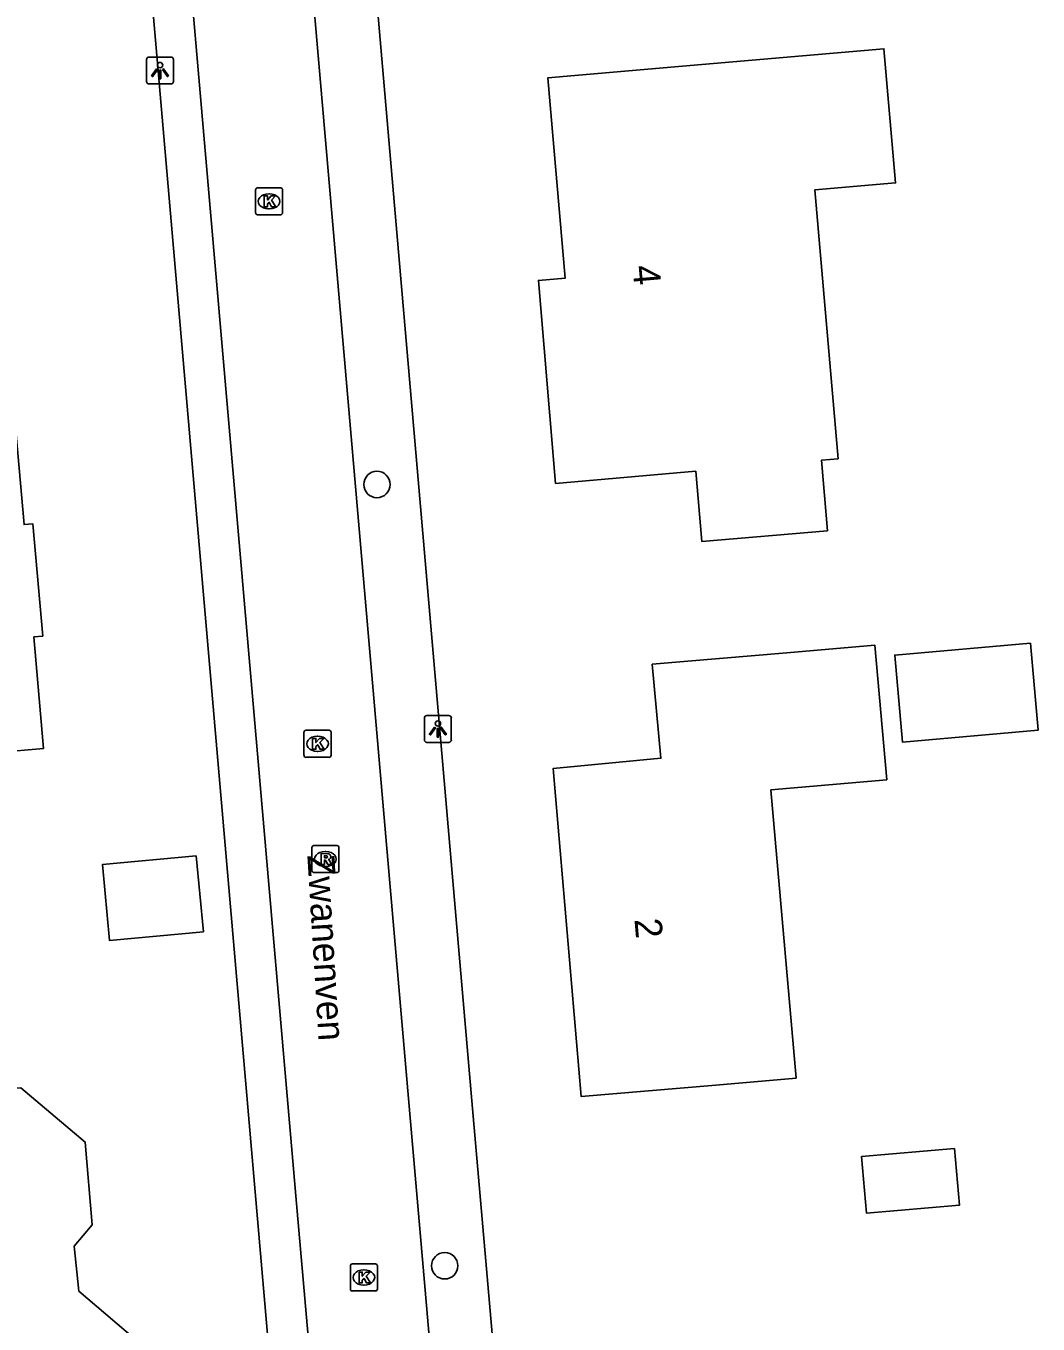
# Model space of a CAD drawing. Extents: x 163427 to 164190, y 380331 to 381641.
# Drawn here: x 164026.23 to 164063.7, y 381087.05 to 381135.13 of the extents above; entities that cross this region are included whole.
import ezdxf

# ---------------------------------------------------------------- set-up
doc = ezdxf.new("R2010")
doc.units = 0
for name, color, linetype in [('IMGEO_Boom', 7, 'Continuous'), ('IMGEO_Kolk', 7, 'Continuous'), ('IMGEO_Lichtpunt', 7, 'Continuous'), ('IMGEO_Openbare_ruimte_label', 7, 'Continuous'), ('IMGEO_Pand', 7, 'Continuous'), ('IMGEO_Pand_nummerreeks', 7, 'Continuous'), ('IMGEO_Rijbaan_lokaal_open', 7, 'Continuous'), ('IMGEO_Rioolput', 7, 'Continuous'), ('IMGEO_Voetpad_open', 7, 'Continuous')]:
    doc.layers.add(name, color=color, linetype=linetype)

msp = doc.modelspace()

# ---------------------------------------------------------------- linework, layer by layer
at = {"layer": 'IMGEO_Boom'}
for centre in [(164039.225, 381118.148), (164041.732, 381089.207)]:
    msp.add_circle(centre, 0.489, dxfattribs=at)
at = {"layer": 'IMGEO_Kolk'}
for p, q in [((164034.728, 381128.211), (164034.728, 381129.063)), ((164034.803, 381129.137), (164035.655, 381129.137)), ((164035.216, 381128.917), (164035.241, 381128.917)), ((164035.729, 381129.063), (164035.729, 381128.211)), ((164035.239, 381128.357), (164035.214, 381128.357)), ((164035.655, 381128.137), (164034.803, 381128.137)), ((164036.522, 381108.115), (164036.522, 381108.967)), ((164036.597, 381109.041), (164037.449, 381109.041)), ((164037.01, 381108.821), (164037.035, 381108.821)), ((164037.523, 381108.967), (164037.523, 381108.115)), ((164037.033, 381108.261), (164037.008, 381108.261)), ((164037.449, 381108.041), (164036.597, 381108.041)), ((164038.238, 381088.346), (164038.238, 381089.198)), ((164038.313, 381089.272), (164039.165, 381089.272)), ((164038.726, 381089.052), (164038.751, 381089.052)), ((164039.239, 381089.198), (164039.239, 381088.346)), ((164038.749, 381088.492), (164038.724, 381088.492)), ((164039.165, 381088.272), (164038.313, 381088.272))]:
    msp.add_line(p, q, dxfattribs=at)
for points in [[(164034.728, 381128.211), (164034.728, 381129.063)], [(164034.803, 381129.137), (164035.655, 381129.137)], [(164035.049, 381128.837), (164035.172, 381128.837), (164035.172, 381128.686), (164035.302, 381128.837), (164035.466, 381128.837), (164035.32, 381128.686), (164035.473, 381128.437), (164035.321, 381128.437), (164035.236, 381128.601), (164035.172, 381128.534), (164035.172, 381128.437), (164035.049, 381128.437), (164035.049, 381128.837)], [(164035.729, 381129.063), (164035.729, 381128.211)], [(164035.655, 381128.137), (164034.803, 381128.137)], [(164036.522, 381108.115), (164036.522, 381108.967)], [(164036.597, 381109.041), (164037.449, 381109.041)], [(164036.843, 381108.741), (164036.966, 381108.741), (164036.966, 381108.59), (164037.096, 381108.741), (164037.26, 381108.741), (164037.114, 381108.59), (164037.267, 381108.341), (164037.115, 381108.341), (164037.03, 381108.505), (164036.966, 381108.438), (164036.966, 381108.341), (164036.843, 381108.341), (164036.843, 381108.741)], [(164037.523, 381108.967), (164037.523, 381108.115)], [(164037.449, 381108.041), (164036.597, 381108.041)], [(164038.238, 381088.346), (164038.238, 381089.198)], [(164038.313, 381089.272), (164039.165, 381089.272)], [(164038.559, 381088.972), (164038.682, 381088.972), (164038.682, 381088.821), (164038.812, 381088.972), (164038.976, 381088.972), (164038.83, 381088.821), (164038.983, 381088.572), (164038.831, 381088.572), (164038.746, 381088.736), (164038.682, 381088.669), (164038.682, 381088.572), (164038.559, 381088.572), (164038.559, 381088.972)], [(164039.239, 381089.198), (164039.239, 381088.346)], [(164039.165, 381088.272), (164038.313, 381088.272)]]:
    msp.add_lwpolyline(points, dxfattribs=at)
for centre, start, end in [((164034.805, 381129.061), 91.552, 178.448), ((164034.805, 381129.061), 91.552, 178.448), ((164035.653, 381129.061), 1.552, 88.448), ((164035.653, 381129.061), 1.552, 88.448), ((164034.805, 381128.213), 181.552, 268.448), ((164034.805, 381128.213), 181.552, 268.448), ((164035.653, 381128.213), 271.552, 358.448), ((164035.653, 381128.213), 271.552, 358.448), ((164036.599, 381108.965), 91.552, 178.448), ((164036.599, 381108.965), 91.552, 178.448), ((164037.447, 381108.965), 1.552, 88.448), ((164037.447, 381108.965), 1.552, 88.448), ((164036.599, 381108.117), 181.552, 268.448), ((164036.599, 381108.117), 181.552, 268.448), ((164037.447, 381108.117), 271.552, 358.448), ((164037.447, 381108.117), 271.552, 358.448), ((164038.315, 381089.196), 91.552, 178.448), ((164038.315, 381089.196), 91.552, 178.448), ((164039.163, 381089.196), 1.552, 88.448), ((164039.163, 381089.196), 1.552, 88.448), ((164038.315, 381088.348), 181.552, 268.448), ((164038.315, 381088.348), 181.552, 268.448), ((164039.163, 381088.348), 271.552, 358.448), ((164039.163, 381088.348), 271.552, 358.448)]:
    msp.add_arc(centre, 0.0765, start, end, dxfattribs=at)
for centre, major_axis, ratio, start_param, end_param in [((164035.215, 381128.637), (-0.387, 0.002), 0.722429, 4.712389, 7.853982), ((164035.24, 381128.637), (-0.39, 0.002), 0.717154, 1.570796, 4.712389), ((164037.009, 381108.541), (-0.387, 0.002), 0.722429, 4.712389, 7.853982), ((164037.034, 381108.541), (-0.39, 0.002), 0.717154, 1.570796, 4.712389), ((164038.725, 381088.772), (-0.387, 0.002), 0.722429, 4.712389, 7.853982), ((164038.75, 381088.772), (-0.39, 0.002), 0.717154, 1.570796, 4.712389)]:
    msp.add_ellipse(centre, major_axis=major_axis, ratio=ratio, start_param=start_param, end_param=end_param, dxfattribs=at)
at = {"layer": 'IMGEO_Lichtpunt'}
for p, q in [((164030.692, 381133.885), (164030.692, 381133.078)), ((164030.692, 381133.885), (164030.692, 381133.078)), ((164031.594, 381133.98), (164030.786, 381133.98)), ((164031.594, 381133.98), (164030.786, 381133.98)), ((164031.688, 381133.078), (164031.688, 381133.885)), ((164031.688, 381133.078), (164031.688, 381133.885)), ((164030.786, 381132.984), (164031.594, 381132.984)), ((164030.786, 381132.984), (164031.594, 381132.984)), ((164041.884, 381109.591), (164041.076, 381109.591)), ((164041.884, 381109.591), (164041.076, 381109.591)), ((164040.982, 381109.496), (164040.982, 381108.689)), ((164040.982, 381109.496), (164040.982, 381108.689)), ((164041.978, 381108.689), (164041.978, 381109.496)), ((164041.978, 381108.689), (164041.978, 381109.496)), ((164041.076, 381108.595), (164041.884, 381108.595)), ((164041.076, 381108.595), (164041.884, 381108.595))]:
    msp.add_line(p, q, dxfattribs=at)
for points in [[(164031.066, 381133.549), (164031.105, 381133.521), (164030.917, 381133.259), (164030.879, 381133.286), (164031.066, 381133.549)], [(164031.168, 381133.501), (164031.215, 381133.501), (164031.215, 381133.179), (164031.168, 381133.179), (164031.168, 381133.501)], [(164031.278, 381133.521), (164031.316, 381133.548), (164031.503, 381133.286), (164031.464, 381133.258), (164031.278, 381133.521)], [(164041.356, 381109.16), (164041.395, 381109.132), (164041.207, 381108.87), (164041.169, 381108.897), (164041.356, 381109.16)], [(164041.458, 381109.112), (164041.505, 381109.112), (164041.505, 381108.79), (164041.458, 381108.79), (164041.458, 381109.112)], [(164041.568, 381109.132), (164041.606, 381109.159), (164041.793, 381108.897), (164041.754, 381108.869), (164041.568, 381109.132)]]:
    msp.add_lwpolyline(points, dxfattribs=at)
for centre in [(164031.191, 381133.683), (164041.481, 381109.294)]:
    msp.add_circle(centre, 0.0994, dxfattribs=at)
for centre, start, end in [((164030.786, 381133.885), 90, 180), ((164030.786, 381133.885), 90, 180), ((164031.594, 381133.885), 0, 90), ((164031.594, 381133.885), 0, 90), ((164030.786, 381133.078), 180, 270), ((164030.786, 381133.078), 180, 270), ((164031.594, 381133.078), 270, 0), ((164031.594, 381133.078), 270, 360), ((164041.076, 381109.496), 90, 180), ((164041.076, 381109.496), 90, 180), ((164041.884, 381109.496), 0, 90), ((164041.884, 381109.496), 0, 90), ((164041.076, 381108.689), 180, 270), ((164041.076, 381108.689), 180, 270), ((164041.884, 381108.689), 270, 0), ((164041.884, 381108.689), 270, 360)]:
    msp.add_arc(centre, 0.0946, start, end, dxfattribs=at)
at = {"layer": 'IMGEO_Pand'}
for points in [[(164056.308, 381119.097), (164055.68, 381119.043), (164055.907, 381116.435), (164051.259, 381116.03), (164051.032, 381118.639), (164045.837, 381118.186), (164045.204, 381125.706), (164046.197, 381125.792), (164045.553, 381133.214), (164050.535, 381133.644), (164057.995, 381134.288), (164058.427, 381129.321), (164055.441, 381129.061), (164056.308, 381119.097)], [(164022.897, 381123.306), (164023.13, 381120.616), (164025.79, 381120.844), (164026.154, 381116.66), (164026.483, 381116.689), (164026.847, 381112.53), (164026.52, 381112.502), (164026.87, 381108.365), (164023.483, 381108.073), (164023.561, 381107.178)], [(164054.748, 381096.152), (164051.772, 381095.898), (164046.79, 381095.474), (164045.751, 381107.631), (164049.742, 381108.005), (164049.416, 381111.488), (164054.398, 381111.914), (164057.666, 381112.193), (164058.103, 381107.211), (164053.81, 381106.834), (164054.748, 381096.152)], [(164063.704, 381109.045), (164058.68, 381108.607), (164058.399, 381111.831), (164063.423, 381112.269), (164063.704, 381109.045)], [(164032.534, 381104.395), (164029.056, 381104.07), (164029.319, 381101.257), (164032.797, 381101.582), (164032.534, 381104.395)], [(164026.032, 381095.799), (164028.413, 381093.79), (164028.676, 381090.719), (164028.013, 381089.931), (164028.186, 381088.27), (164030.609, 381086.198), (164030.975, 381081.841), (164028.167, 381078.484), (164023.8, 381078.126), (164019.504, 381081.734), (164019.312, 381084.422), (164021.285, 381086.767), (164022.893, 381088.678), (164021.235, 381090.089), (164020.964, 381093.173), (164022.955, 381095.537), (164026.032, 381095.799)], [(164060.612, 381093.554), (164060.797, 381091.454), (164057.356, 381091.152), (164057.172, 381093.251), (164060.612, 381093.554)]]:
    msp.add_lwpolyline(points, dxfattribs=at)
at = {"layer": 'IMGEO_Rijbaan_lokaal_open'}
for points in [[(164035.572, 381151.02), (164040.416, 381095.118), (164043.083, 381064.431)], [(164038.683, 381063.659), (164036.27, 381091.227), (164031.138, 381150.457)]]:
    msp.add_lwpolyline(points, dxfattribs=at)
at = {"layer": 'IMGEO_Rioolput'}
for p, q in [((164036.89, 381104.774), (164037.742, 381104.774)), ((164036.815, 381103.848), (164036.815, 381104.7)), ((164037.303, 381104.554), (164037.328, 381104.554)), ((164037.816, 381104.7), (164037.816, 381103.848)), ((164037.326, 381103.994), (164037.301, 381103.994)), ((164037.742, 381103.774), (164036.89, 381103.774))]:
    msp.add_line(p, q, dxfattribs=at)
for points in [[(164036.89, 381104.774), (164037.742, 381104.774)], [(164036.815, 381103.848), (164036.815, 381104.7)], [(164037.404, 381104.472), (164037.152, 381104.474), (164037.152, 381104.074)], [(164037.33, 381104.393), (164037.276, 381104.393), (164037.276, 381104.312)], [(164037.276, 381104.312), (164037.328, 381104.312)], [(164037.816, 381104.7), (164037.816, 381103.848)], [(164037.152, 381104.074), (164037.276, 381104.074), (164037.276, 381104.236), (164037.287, 381104.236)], [(164037.334, 381104.207), (164037.405, 381104.074), (164037.545, 381104.074), (164037.48, 381104.2)], [(164037.742, 381103.774), (164036.89, 381103.774)]]:
    msp.add_lwpolyline(points, dxfattribs=at)
for centre, radius, start, end in [((164036.892, 381104.698), 0.0765, 91.552, 178.448), ((164036.892, 381104.698), 0.0765, 91.552, 178.448), ((164037.74, 381104.698), 0.0765, 1.552, 88.448), ((164037.74, 381104.698), 0.0765, 1.552, 88.448), ((164037.312, 381104.501), 0.19, 274.7715, 282.9687), ((164037.336, 381104.297), 0.0964, 77.0061, 93.1865), ((164037.35, 381104.354), 0.0378, 276.6634, 79.6772), ((164037.403, 381104.362), 0.109, 350.3612, 89.416), ((164037.401, 381104.362), 0.112, 277.5842, 350.9817), ((164036.892, 381103.85), 0.0765, 181.552, 268.448), ((164036.892, 381103.85), 0.0765, 181.552, 268.448), ((164037.286, 381104.183), 0.0533, 26.0293, 88.6989), ((164037.385, 381104.147), 0.108, 29.5134, 73.7905), ((164037.74, 381103.85), 0.0765, 271.552, 358.448), ((164037.74, 381103.85), 0.0765, 271.552, 358.448)]:
    msp.add_arc(centre, radius, start, end, dxfattribs=at)
for centre, major_axis, ratio, start_param, end_param in [((164037.302, 381104.274), (-0.387, 0.002), 0.722429, 4.712389, 7.853982), ((164037.327, 381104.274), (-0.39, 0.002), 0.717154, 1.570796, 4.712389)]:
    msp.add_ellipse(centre, major_axis=major_axis, ratio=ratio, start_param=start_param, end_param=end_param, dxfattribs=at)
at = {"layer": 'IMGEO_Voetpad_open'}
for points in [[(164037.905, 381151.233), (164042.738, 381095.311), (164045.412, 381064.621)], [(164036.83, 381067.54), (164029.665, 381150.318)]]:
    msp.add_lwpolyline(points, dxfattribs=at)

# ---------------------------------------------------------------- texts
at = {"layer": 'IMGEO_Openbare_ruimte_label'}
msp.add_text('Zwanenven', height=1, rotation=273.4977, dxfattribs=at).set_placement((164036.644, 381104.413))
at = {"layer": 'IMGEO_Pand_nummerreeks'}
for s, rotation, p in [('4', 274.9616, (164048.688, 381126.237)), ('2', 274.8849, (164048.758, 381102.043))]:
    msp.add_text(s, height=1, rotation=rotation, dxfattribs=at).set_placement(p)

doc.saveas('drawing.dxf')
